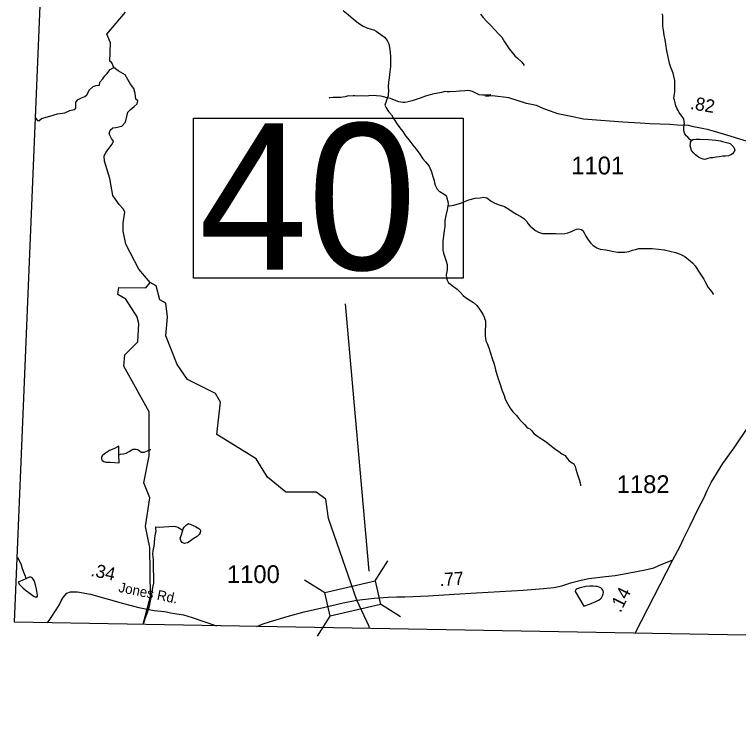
# Model space of a CAD drawing. Extents: x 1950930 to 2061844, y 904556 to 1017002.
# Drawn here: x 1954667 to 1961592, y 906013 to 912890 of the extents above; entities that cross this region are included whole.
import ezdxf

# ---------------------------------------------------------------- set-up
doc = ezdxf.new("R2010")
doc.units = 0
for name, color, linetype in [('Exist Boundary Political CountyLine', 7, 'Continuous'), ('Exist Hydrographic Creek Single Shore', 7, 'Continuous'), ('Exist Hydrographic Misc Water Feature', 7, 'Continuous'), ('Exist Road Non-System Type 51', 7, 'Continuous'), ('Exist Road Primary US Structure Standard Bridge CELL', 7, 'Continuous'), ('Exist Road Secondary Structure Standard Bridge CELL', 7, 'Continuous'), ('Exist Road Secondary Structure Standard Bridge Number Label', 7, 'Continuous'), ('Exist Road Secondary Type 41 Attributed', 7, 'Continuous'), ('Exist Road Secondary Type 51 Attributed', 7, 'Continuous'), ('Exist Road Secondary Type 51 Label', 7, 'Continuous'), ('Exist Road Secondary Type 51 Number Label', 7, 'Continuous')]:
    doc.layers.add(name, color=color, linetype=linetype)

msp = doc.modelspace()

# ---------------------------------------------------------------- linework, layer by layer
at = {"layer": 'Exist Boundary Political CountyLine'}
for points in [[(1954666.9, 907077.7), (1956979.8, 962278.8), (1958720.5, 998184), (1959482.1, 1016167.2)], [(2014538, 906012.8), (1997082.5, 906396.5), (1993199.8, 906445.3), (1978988.5, 906730.2), (1974332.2, 906819.9), (1966688.7, 906863.1), (1954666.9, 907077.7)]]:
    msp.add_lwpolyline(points, dxfattribs=at)
at = {"layer": 'Exist Hydrographic Creek Single Shore'}
for points in [[(1955616.2, 912381.1), (1955597.5, 912426.8), (1955579.8, 912444.6), (1955584.5, 912619.6), (1955551.5, 912702.4), (1955727.6, 912912.1)], [(1957809.2, 912926.2), (1957857.2, 912888.2), (1957909.1, 912844.1), (1957952.9, 912810.1), (1957996.8, 912779.9), (1958036.8, 912761.9), (1958076.8, 912749.8), (1958102.8, 912741.7), (1958124.8, 912729.7), (1958170.7, 912699.5), (1958206.6, 912673.5), (1958230.6, 912641.5), (1958246.6, 912609.4), (1958254.6, 912575.4), (1958258.5, 912529.3), (1958262.4, 912481.4), (1958264.2, 912437.4), (1958262.2, 912391.3), (1958256, 912341.4), (1958251.9, 912283.4), (1958243.9, 912241.3), (1958241.7, 912199.4), (1958243.7, 912159.4), (1958241.7, 912123.3), (1958239.6, 912111.3), (1958225.5, 912071.5), (1958217.5, 912049.4), (1958211.5, 912033.4), (1958209.5, 912021.4), (1958221.4, 911995.4), (1958243.3, 911961.3), (1958271.2, 911929.4), (1958299.3, 911885.3), (1958327.2, 911841.2), (1958350.9, 911807.1), (1958381.1, 911771.1), (1958406.9, 911729), (1958441, 911687), (1958476.8, 911638.9), (1958508.6, 911600.8), (1958542.7, 911554.7), (1958572.4, 911510.6), (1958596.6, 911480.6), (1958632.3, 911440.5), (1958654.2, 911384.5), (1958668.2, 911338.5), (1958680.1, 911300.5), (1958684.2, 911278.4), (1958690.1, 911258.4), (1958698.1, 911244.4), (1958710, 911218.4), (1958725.8, 911202.3), (1958745.9, 911190.4), (1958759.8, 911180.3), (1958777.9, 911170.3), (1958790, 911160.2), (1958798, 911148.2), (1958801.9, 911134.3), (1958811.7, 911102.2), (1958813.5, 911080.1), (1958811.7, 911058.2)], [(1959123.2, 912893.8), (1959149.2, 912859.8), (1959183, 912823.7), (1959221, 912787.6), (1959261, 912741.6), (1959294.8, 912703.4), (1959326.8, 912671.4), (1959354.7, 912629.3), (1959378.7, 912591.3), (1959398.6, 912561.2), (1959426.4, 912527.2), (1959452.5, 912495.2), (1959478.3, 912471.1), (1959512.4, 912439), (1959532.3, 912417), (1959542.3, 912402.9)], [(1961141.1, 911683.9), (1961127.1, 911693.9), (1961107.1, 911715.9), (1961091.1, 911729.9), (1961077.1, 911748), (1961069.3, 911776), (1961069.3, 911802), (1961073.4, 911838), (1961075.5, 911848.1), (1961073.4, 911863.9), (1961067.5, 911890.1), (1961053.5, 911914.1), (1961041.4, 911930.1), (1961025.4, 911952.1), (1961013.8, 911972.1), (1961005.6, 911988.2), (1960993.7, 912016.2), (1960985.9, 912044.2), (1960977.9, 912072.3), (1960973.8, 912090.2), (1960975.8, 912108.3), (1960982, 912152.1), (1960984, 912192.2), (1960984, 912218.3), (1960982.2, 912258.3), (1960974.2, 912298.2), (1960966.2, 912328.3), (1960954.3, 912360.3), (1960944.4, 912382.3), (1960934.4, 912410.3), (1960924.6, 912452.3), (1960916.6, 912496.4), (1960906.7, 912542.4), (1960896.9, 912606.4), (1960888.9, 912648.5), (1960881.1, 912690.4), (1960873.1, 912740.5), (1960867.1, 912778.5), (1960869.2, 912832.5), (1960867.3, 912872.5), (1960865.3, 912894.5)], [(1954868.9, 911899.4), (1954885.7, 911875.7), (1954899.7, 911871), (1954926.8, 911895.3), (1955004.3, 911916.8), (1955078.9, 911939.2), (1955149, 911949.5), (1955197.5, 911971), (1955237.6, 911981.2), (1955254, 911994.3), (1955254.9, 912052.2), (1955275.5, 912075.6), (1955307.2, 912091.5), (1955340.8, 912106.4), (1955360.4, 912120.4), (1955383.7, 912169.9), (1955419.2, 912201.7), (1955447.7, 912210.1), (1955478.5, 912214.8), (1955483.2, 912240.9), (1955512.1, 912272.7), (1955529.8, 912303.5), (1955550.8, 912321.3), (1955580.7, 912364.2), (1955616.2, 912381.1)], [(1955963.4, 910327.6), (1955855.2, 910454.8), (1955731.5, 910693.4), (1955705.8, 910817.3), (1955707.7, 910898.5), (1955722.1, 910997.6), (1955710.9, 911027.4), (1955668.9, 911071.4), (1955628.8, 911125.5), (1955608.3, 911159.2), (1955577.4, 911320.8), (1955528, 911485.2), (1955524.2, 911533.8), (1955541.5, 911569.3), (1955599.9, 911650.5), (1955612.9, 911677.6), (1955593.3, 911702.9), (1955572.8, 911749.6), (1955583.5, 911783.2), (1955607.8, 911805.6), (1955635.8, 911810.3), (1955695.1, 911820.6), (1955729.6, 911859.8), (1955742.7, 911914.9), (1955750.1, 911956), (1955773, 911978.4), (1955810.4, 912008.3), (1955840.2, 912036.4), (1955845.8, 912063.4), (1955829, 912080.3), (1955819.7, 912134.4), (1955808.5, 912180.2), (1955776.3, 912223.2), (1955726.3, 912311), (1955659.1, 912352.1), (1955616.2, 912381.1)], [(1958811.7, 911058.2), (1958827.7, 911060.1), (1958867.7, 911066.1), (1958901.7, 911074.1), (1958935.8, 911086), (1958979.8, 911103.8), (1959011.8, 911115.8), (1959071.7, 911131.7), (1959121.9, 911135.6), (1959156, 911141.6), (1959172, 911139.5), (1959185.9, 911135.5), (1959225.7, 911105.5), (1959261.8, 911085.4), (1959301.8, 911069.3), (1959353.9, 911053.2), (1959395.7, 911027), (1959435.7, 910999), (1959467.7, 910980.9), (1959497.6, 910964.9), (1959509.5, 910958.8), (1959537.6, 910938.8), (1959565.5, 910910.8), (1959579.4, 910888.7), (1959597.5, 910864.7), (1959613.5, 910852.6), (1959633.3, 910836.6), (1959649.3, 910824.5), (1959677.2, 910808.5), (1959715.4, 910796.4), (1959753.3, 910794.4), (1959799.2, 910796.3), (1959843.3, 910796.2), (1959895.2, 910792.1), (1959931.3, 910794.1), (1959959.2, 910800), (1959995.3, 910814), (1960025.4, 910829.9), (1960041.4, 910837.9), (1960057.4, 910839.8), (1960075.4, 910835.7), (1960089.4, 910831.7), (1960101.5, 910823.7), (1960115.2, 910801.7), (1960131.2, 910769.7), (1960153.1, 910733.6), (1960175.1, 910705.6), (1960200.9, 910679.6), (1960235, 910657.4), (1960269, 910645.3), (1960322.9, 910637.2), (1960355.1, 910631.3), (1960399, 910623.1), (1960433, 910617), (1960505, 910616.9), (1960543, 910622.9), (1960577, 910634.9), (1960605.1, 910642.8), (1960639.1, 910650.7), (1960696.9, 910652.6), (1960767.1, 910650.5), (1960825.1, 910646.3), (1960879, 910638.1), (1960935, 910626.2), (1960988.9, 910614.1), (1961033, 910598), (1961079, 910575.9), (1961114.8, 910547.7), (1961153, 910513.7), (1961176.8, 910485.6), (1961202.6, 910445.6), (1961222.7, 910415.6), (1961240.7, 910385.5), (1961258.6, 910357.5), (1961262.5, 910351.5), (1961276.6, 910327.5), (1961302.5, 910279.4), (1961324.4, 910251.4), (1961340.2, 910231.3), (1961348.2, 910215.3), (1961352.3, 910215.3)], [(1958811.7, 911058.2), (1958805.5, 911020.2), (1958793.4, 910968.2), (1958783.4, 910918.2), (1958781.4, 910862.3), (1958777.3, 910822.2), (1958769, 910770.2), (1958764.9, 910726.2), (1958763.1, 910702.2), (1958762.9, 910674.2), (1958762.9, 910646.2), (1958762.9, 910636.2), (1958768.8, 910606.3), (1958784.8, 910558.2), (1958796.7, 910530.2), (1958804.7, 910498.1), (1958806.6, 910476.2), (1958804.5, 910446.1), (1958796.3, 910398.1), (1958798.4, 910368.2), (1958804.3, 910348.1), (1958818.3, 910324.1), (1958834.3, 910312), (1958852.3, 910298.1), (1958900.1, 910261.9), (1958932.1, 910231.8), (1958958.1, 910201.8), (1958980, 910181.8), (1959014.1, 910159.7), (1959055.9, 910135.6), (1959089.1, 910107.7), (1959115.8, 910070.2), (1959146.5, 910022.4), (1959160.9, 909988.4), (1959160.9, 909982.4), (1959171, 909958.4), (1959172.8, 909916.4), (1959168.7, 909866.4), (1959168.7, 909812.4), (1959170.5, 909792.4), (1959176.5, 909768.3), (1959186.3, 909744.3), (1959202.3, 909702.3), (1959218.3, 909650.3), (1959236.2, 909600.3), (1959254, 909544.2), (1959267.9, 909490.2), (1959283.9, 909436.1), (1959293.8, 909406.1), (1959301.8, 909380.1), (1959313.7, 909342), (1959327.6, 909300), (1959349.6, 909245.9), (1959361.4, 909211.9), (1959383.4, 909167.9), (1959407.2, 909125.8), (1959433.2, 909089.8), (1959467.3, 909053.7), (1959489.2, 909025.7), (1959515, 908997.6), (1959545, 908967.6), (1959564.9, 908947.5), (1959580.8, 908933.5), (1959595, 908925.5), (1959603, 908919.4), (1959612.8, 908911.4), (1959622.7, 908897.4), (1959638.7, 908879.4), (1959668.8, 908855.3), (1959716.8, 908825.2), (1959752.7, 908801.1), (1959786.7, 908775), (1959832.4, 908739), (1959872.4, 908708.9), (1959902.6, 908688.8), (1959932.3, 908670.8), (1959944.4, 908656.7), (1959958.4, 908636.7), (1959970.2, 908624.7), (1959986.2, 908610.7), (1960000.2, 908602.6), (1960010.2, 908594.6), (1960016.4, 908590.6), (1960022.3, 908580.6), (1960028.3, 908566.6), (1960036.1, 908540.6), (1960044.1, 908510.5), (1960058, 908472.5), (1960068.1, 908442.6), (1960075.8, 908410.5), (1960079.9, 908388.4), (1960079.9, 908380.4)], [(1956131.6, 909999.2), (1956113.5, 910127.6), (1956055.5, 910161.6), (1956022.5, 910293.6), (1955963.4, 910327.6)], [(1958059.4, 907021.9), (1958058.7, 907035.4), (1957942.6, 907286.6), (1957669.5, 908070.7), (1957644.7, 908254.9), (1957553.6, 908322.5), (1957261.6, 908321.9), (1957086.5, 908463.3), (1956978.7, 908639.5), (1956603.6, 908873.7), (1956638.5, 909181.4), (1956588.6, 909264.5), (1956321.4, 909398), (1956222.6, 909541.2), (1956114.5, 909815.8), (1956131.2, 909995.7)]]:
    msp.add_lwpolyline(points, dxfattribs=at)
at = {"layer": 'Exist Hydrographic Misc Water Feature'}
msp.add_line((1955969.1, 908729.1), (1955972.1, 908730.4), dxfattribs=at)
for points in [[(1961141.1, 911683.9), (1961155.2, 911693.9), (1961187.2, 911695.8), (1961221.1, 911697.8), (1961305.1, 911693.6), (1961373.2, 911687.4), (1961418.9, 911681.4), (1961439, 911675.3), (1961465.1, 911669.3), (1961489.1, 911663.2), (1961511, 911655.2), (1961529, 911641.2), (1961543, 911623.1), (1961551, 911611.1), (1961554.9, 911593.1), (1961551, 911583.1), (1961546.9, 911573.1), (1961535, 911557.1), (1961518.8, 911547.1), (1961496.9, 911539.1), (1961466.7, 911535.3), (1961440.9, 911533.3), (1961406.8, 911527.4), (1961378.7, 911525.4), (1961346.8, 911519.5), (1961320.7, 911517.5), (1961296.7, 911511.6), (1961270.7, 911503.6), (1961252.8, 911505.6), (1961234.8, 911511.7), (1961208.8, 911525.7), (1961180.9, 911545.8), (1961162.8, 911563.8), (1961142.9, 911589.9), (1961134.9, 911611.8), (1961129, 911631.9), (1961131, 911655.8), (1961133.1, 911669.9), (1961141.1, 911683.9)], [(1955839.6, 909998.7), (1955730.5, 910168.4), (1955655.4, 910212.5), (1955663.4, 910278), (1955922.6, 910275.9), (1955963.4, 910327.6)], [(1955897.7, 907057.2), (1955967.5, 907324.5), (1955960.6, 907790.7), (1955918.5, 907991.7), (1955961.6, 908266.6), (1955903.6, 908408.9), (1955953.6, 908667.1), (1955954.6, 909090.5), (1955713.5, 909525.3), (1955722.5, 909633.5), (1955847.6, 909759), (1955856.6, 909932.6), (1955840.2, 909996.2)], [(1955840.2, 909996.2), (1955839.6, 909998.7)], [(1956131.2, 909995.7), (1956131.6, 909999.2)], [(1955666.2, 908679.1), (1955666.2, 908689), (1955664.1, 908761), (1955618, 908737.1), (1955576.2, 908719.2), (1955528.2, 908687.3), (1955506.1, 908667.4), (1955499.9, 908651.4), (1955499.9, 908635.4), (1955506.1, 908623.3), (1955521.8, 908613.3), (1955541.9, 908609.3), (1955563.9, 908607.2), (1955581.9, 908607.2), (1955667.8, 908603), (1955666.2, 908679.1)], [(1955666.2, 908679.1), (1955680.1, 908683), (1955708, 908688.9), (1955734.1, 908695), (1955744.1, 908698.9), (1955764, 908708.8), (1955790.1, 908726.8), (1955802.1, 908730.8), (1955818.1, 908732.7), (1955832.3, 908732.7), (1955846.2, 908728.7), (1955858.1, 908718.7), (1955866.1, 908712.6), (1955874.1, 908706.7), (1955880.1, 908704.6), (1955890.1, 908702.7), (1955906.1, 908704.5), (1955924.2, 908708.5), (1955940.1, 908716.5), (1955969.1, 908729.1)], [(1956014.8, 907990.3), (1956016.8, 907970.3), (1956018.7, 907946.3), (1956012.5, 907922.3), (1956006.6, 907884.3), (1956002.5, 907836.3), (1955998.4, 907800.3), (1955994.3, 907778.3), (1955990.2, 907756.2), (1955988.3, 907730.3), (1955990.2, 907700.4), (1955992, 907684.3), (1955992, 907580.3), (1955995.9, 907520.3), (1955997.8, 907484.2), (1955995.7, 907452.3), (1955987.7, 907410.3), (1955979.5, 907364.3), (1955963.3, 907282.3), (1955951.2, 907218.3), (1955937.1, 907166.3), (1955914.9, 907110.4), (1955901, 907068.4), (1955896, 907055.7)], [(1956014.8, 907990.3), (1956052.7, 907986.2), (1956096.8, 907988.2), (1956142.7, 907994), (1956184.8, 907995.9), (1956206.7, 907993.9), (1956230.7, 907987.8), (1956246.7, 907977.9), (1956262.7, 907963.8), (1956276.8, 907953.8)], [(1956276.8, 907953.8), (1956280.7, 907969.8), (1956288.7, 907985.8), (1956310.7, 908007.7), (1956326.9, 908019.6), (1956332.8, 908021.7), (1956398.6, 907991.5), (1956430.8, 907973.5), (1956438.8, 907967.4), (1956444.8, 907955.5), (1956442.5, 907933.5), (1956432.7, 907915.5), (1956412.6, 907897.5), (1956376.7, 907873.6), (1956338.6, 907845.6), (1956320.5, 907835.7), (1956304.5, 907833.8), (1956294.5, 907831.7), (1956284.4, 907833.8), (1956270.5, 907839.8), (1956256.5, 907859.8), (1956252.6, 907879.8), (1956262.7, 907911.8), (1956272.7, 907945.8), (1956276.8, 907953.8)], [(1954694.3, 907698), (1954700, 907688.8), (1954718, 907654.7), (1954729.9, 907626.8), (1954741.8, 907590.7), (1954757.8, 907550.7), (1954767.7, 907518.6), (1954775.7, 907492.6)], [(1954775.7, 907492.6), (1954767.7, 907490.6), (1954701.6, 907460.8), (1954713.5, 907436.8), (1954747.6, 907404.7), (1954773.4, 907384.6), (1954795.5, 907368.6), (1954805.4, 907362.5), (1954855.4, 907322.5), (1954865.3, 907320.4), (1954875.3, 907318.5), (1954881.3, 907318.4), (1954887.4, 907326.4), (1954887.4, 907336.4), (1954877.6, 907392.5), (1954863.6, 907448.5), (1954853.6, 907476.4), (1954839.6, 907498.5), (1954829.8, 907506.5), (1954819.7, 907508.5), (1954805.8, 907506.6), (1954775.7, 907492.6)], [(1960081.8, 907284.3), (1960113.6, 907230.3), (1960167.7, 907250.2), (1960227.8, 907276), (1960253.8, 907288), (1960267.8, 907298), (1960279.9, 907312), (1960289.9, 907329.9), (1960295.9, 907349.9), (1960300, 907361.9), (1960295.9, 907381.9), (1960285.8, 907396), (1960274.1, 907406), (1960242.1, 907418), (1960228, 907420.2), (1960200.1, 907422.1), (1960170, 907422.2), (1960132, 907418.2), (1960076.1, 907406.3), (1960048, 907396.5), (1960040, 907390.5), (1960034, 907382.5), (1960029.9, 907372.4), (1960081.8, 907284.3)]]:
    msp.add_lwpolyline(points, dxfattribs=at)
at = {"layer": 'Exist Road Non-System Type 51'}
msp.add_lwpolyline([(1959223.1, 912121.4), (1959221.1, 912121.7), (1959206.2, 912118.4), (1959174.1, 912116.4), (1959144, 912117.4), (1959110.9, 912122.6), (1959087, 912132.9), (1959060.1, 912145.4), (1959048.8, 912151.6), (1959034.2, 912155.8), (1959024.9, 912157.8), (1958999, 912163), (1958974.1, 912160.9), (1958924.4, 912156.8), (1958891.2, 912151.6), (1958828, 912150.6), (1958804.2, 912150.6), (1958786.6, 912151.6), (1958751.4, 912143.3), (1958665.4, 912126.8), (1958597, 912108.1), (1958546.2, 912090.5), (1958470.1, 912064.1), (1958420.4, 912051.6), (1958400.6, 912047.5), (1958382, 912047.5), (1958341.6, 912053.7), (1958318.8, 912063), (1958263.9, 912084.8), (1958219.4, 912097.2), (1958188.2, 912105.5), (1958169.1, 912108.1), (1958128.6, 912112.2), (1958103.9, 912113.2), (1958055.1, 912112.2), (1958029.2, 912109.1), (1957989.9, 912110.2), (1957944.2, 912109.1), (1957922.5, 912110.2), (1957904.9, 912111.2), (1957849, 912108.1), (1957830.2, 912102.9), (1957808.5, 912097.8), (1957786.8, 912095.6), (1957772.2, 912096.7), (1957737, 912096.7), (1957713.2, 912094.6), (1957681.1, 912092.6), (1957673.4, 912089.6)], dxfattribs=at)
at = {"layer": 'Exist Road Secondary Structure Standard Bridge CELL'}
for p, q in [((1958117.1, 907472.2), (1958237.1, 907664.2)), ((1957441.9, 907481.9), (1957633.8, 907361.9)), ((1958168, 907251.7), (1958359.9, 907131.7)), ((1957565.8, 906944.3), (1957685.8, 907136.2))]:
    msp.add_line(p, q, dxfattribs=at)
msp.add_lwpolyline([(1957633.8, 907361.9), (1958116.9, 907473.3), (1958168.9, 907247.6), (1957685.8, 907136.2)], close=True, dxfattribs=at)
at = {"layer": 'Exist Road Secondary Structure Standard Bridge Number Label'}
msp.add_line((1958060.7, 907566.5), (1957833.7, 910121.9), dxfattribs=at)
msp.add_lwpolyline([(1956380.6, 911898.1), (1958957.2, 911898.1), (1958957.2, 910368.9), (1956380.6, 910368.9)], close=True, dxfattribs=at)
at = {"layer": 'Exist Road Secondary Type 41 Attributed'}
for points in [[(1961676.9, 911674.3), (1961479.1, 911735.6), (1961363.4, 911770.2), (1961295.6, 911790.6), (1961259.5, 911796.9), (1961213.6, 911805.1), (1961161.9, 911815.5), (1961114, 911827.9), (1961009.6, 911832.1), (1960933.6, 911836.7), (1960743.7, 911844), (1960651.8, 911850.7), (1960483.7, 911859.7), (1960275.7, 911875), (1960107.8, 911889.9), (1959990, 911912.7), (1959862.1, 911939.6), (1959792.2, 911963.8), (1959728.3, 911986.3), (1959660.5, 912018.7), (1959564.7, 912039.3), (1959393.6, 912092.2), (1959239.8, 912113), (1959170.9, 912103.7)], [(1954983.2, 907072), (1955012.2, 907112.3), (1955065.4, 907195.5), (1955096.2, 907246.9), (1955113.5, 907281.8), (1955133.3, 907313.1), (1955168.6, 907355.2), (1955201.2, 907367.4), (1955268.4, 907368.3), (1955394.5, 907345.9), (1955708.3, 907255.7), (1955855, 907217.8), (1956001.7, 907189.7), (1956102.6, 907178.7), (1956178.1, 907165.3), (1956283.6, 907148.8), (1956367.1, 907122.8), (1956600.2, 907043.2)]]:
    msp.add_lwpolyline(points, dxfattribs=at)
at = {"layer": 'Exist Road Secondary Type 51 Attributed'}
msp.add_line((1960602.7, 906971.7), (1960963.6, 907674.8), dxfattribs=at)
for points in [[(1960963.6, 907674.8), (1961033, 907805.6), (1961066.9, 907875.8), (1961128.2, 908001.6), (1961205.7, 908162.2), (1961263.8, 908270.3), (1961292.8, 908338.1), (1961331.5, 908413.9), (1961442.9, 908594.7), (1961549.4, 908746.4), (1961681.7, 908940)], [(1957942.6, 907286.6), (1958106.5, 907307.7), (1958240.5, 907317.3), (1958324.4, 907320.7), (1958400.2, 907319.8), (1958625.3, 907328.7), (1958872, 907344.8), (1959084.7, 907358), (1959533.1, 907383.6), (1959727.3, 907399.5), (1959826.2, 907407.8), (1959901, 907424.7), (1959998.6, 907457), (1960087.4, 907478.8), (1960161.2, 907496.6), (1960318.4, 907514.3), (1960410.7, 907522.6), (1960531.9, 907545.7), (1960697.8, 907576.7), (1960780.3, 907598.1), (1960828.1, 907619.6), (1960963.6, 907674.8)], [(1956983.7, 907036.3), (1957034.2, 907057.8), (1957115.3, 907082.9), (1957274.8, 907132.3), (1957437.2, 907175.8), (1957634.4, 907221.4), (1957810.3, 907264), (1957942.6, 907286.6)]]:
    msp.add_lwpolyline(points, dxfattribs=at)

# ---------------------------------------------------------------- texts
at = {"layer": 'Exist Road Primary US Structure Standard Bridge CELL'}
for s, rotation, p in [('.82', 350.10255, (1961124, 911986.3)), ('.34', 348.1328, (1955389.4, 907520.9)), ('.77', 3.55153, (1958735.2, 907422.1)), ('.14', 63.39884, (1960462.9, 907162.1))]:
    msp.add_text(s, height=125, rotation=rotation, dxfattribs=at).set_placement(p)
at = {"layer": 'Exist Road Secondary Structure Standard Bridge Number Label'}
msp.add_text('40', height=1400, dxfattribs=at).set_placement((1956430.8, 910448))
at = {"layer": 'Exist Road Secondary Type 51 Label'}
msp.add_text('Jones Rd.', height=95, rotation=348.58698, dxfattribs=at).set_placement((1955657, 907368.2))
at = {"layer": 'Exist Road Secondary Type 51 Number Label'}
for s, p in [('1101', (1959991.7, 911360.1)), ('1182', (1960426.5, 908312.6)), ('1100', (1956698.7, 907451.8))]:
    msp.add_text(s, height=170, dxfattribs=at).set_placement(p)

doc.saveas('drawing.dxf')
